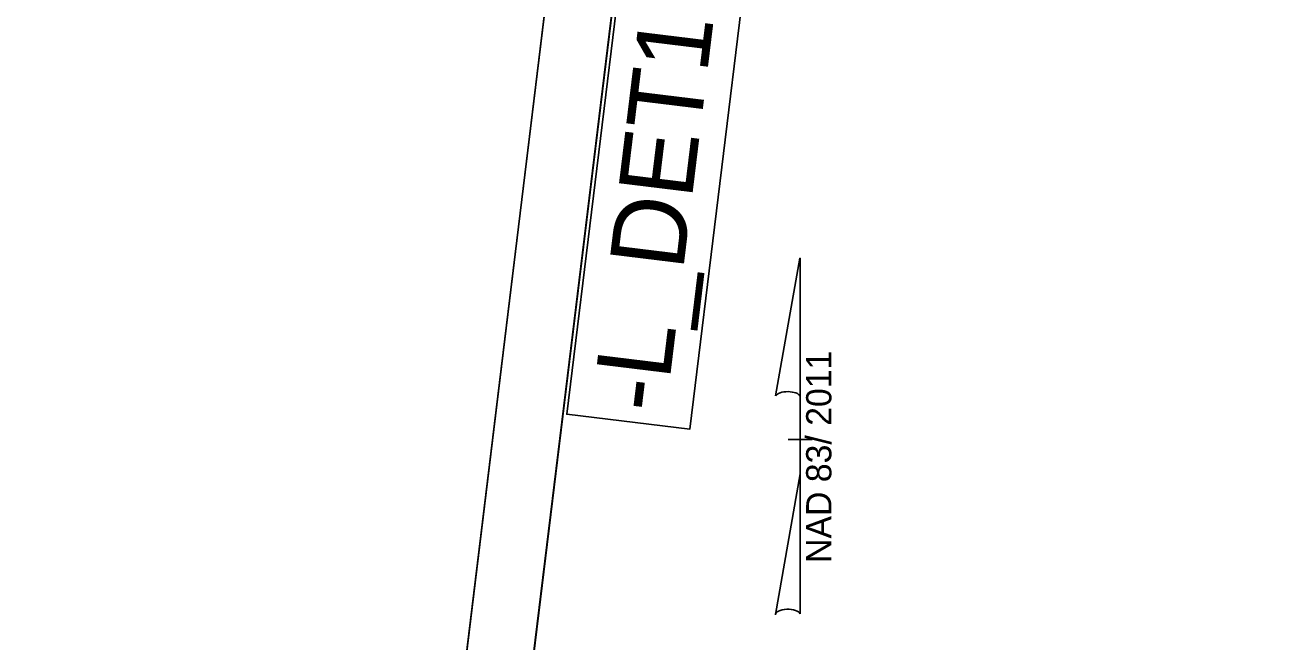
# Model space of a CAD drawing. Extents: x 480344 to 482186, y 488805 to 491553.
# Drawn here: x 480615.8 to 481040.8, y 490157.9 to 490365.2 of the extents above; entities that cross this region are included whole.
import ezdxf

# ---------------------------------------------------------------- set-up
doc = ezdxf.new("R2010")
doc.units = 0
for name, color, linetype in [('Old_Level_1', 7, 'Continuous'), ('Prop Grid Mask', 7, 'Continuous'), ('Prop North Arrow NAD83 for Plan Sheets CELL', 7, 'Continuous'), ('Sheet Cutting Line CELL', 7, 'Continuous'), ('Sheet Layout Plan Border', 7, 'Continuous'), ('Sheet North Arrow Point CELL', 7, 'Continuous'), ('Sheet Plan CELL', 7, 'Continuous'), ('Sheet Plan Layout CELL', 7, 'Continuous'), ('Sheet Plot Border Inside CELL', 7, 'Continuous'), ('Sheet Plot Border Outside CELL', 7, 'Continuous')]:
    doc.layers.add(name, color=color, linetype=linetype)

msp = doc.modelspace()

# ---------------------------------------------------------------- linework, layer by layer
at = {"layer": 'Prop Grid Mask'}
msp.add_lwpolyline([(480817.17, 490390.57), (480798.09, 490234.37), (480839.49, 490229.31), (480858.56, 490385.52)], close=True, dxfattribs=at)
at = {"layer": 'Prop North Arrow NAD83 for Plan Sheets CELL'}
for p, q in [((480868.41, 490240.54), (480876.61, 490286.89)), ((480876.66, 490286.89), (480876.61, 490286.89)), ((480876.66, 490286.89), (480876.61, 490286.89)), ((480876.66, 490286.89), (480876.66, 490239.09)), ((480876.66, 490214.29), (480876.66, 490240.49)), ((480876.66, 490239.09), (480876.66, 490240.44)), ((480872.66, 490225.89), (480872.61, 490225.89)), ((480876.21, 490225.89), (480872.66, 490225.89)), ((480872.71, 490225.89), (480880.71, 490225.89)), ((480876.66, 490214.29), (480868.31, 490167.04)), ((480876.71, 490167.24), (480876.66, 490214.29))]:
    msp.add_line(p, q, dxfattribs=at)
for centre, start_param, end_param in [((480872.54, 490240.04), 0.216388, 2.908219), ((480872.54, 490166.87), 0.201328, 3.141593)]:
    msp.add_ellipse(centre, major_axis=(4.23, -0.03), ratio=0.461098, start_param=start_param, end_param=end_param, dxfattribs=at)
at = {"layer": 'Sheet Cutting Line CELL'}
msp.add_line((480819.86, 490608.9), (480615.75, 488937.82), dxfattribs=at)
at = {"layer": 'Sheet Layout Plan Border'}
msp.add_lwpolyline([(481703.23, 488995.25), (481861.69, 490292.69), (481782.27, 490302.39), (481802.94, 490471.69), (481574.79, 490460.72), (481089.79, 490519.96), (481007.71, 490529.98), (480988.13, 490369.7), (480815.85, 490390.73), (480660.97, 489122.55)], close=True, dxfattribs=at)
at = {"layer": 'Sheet North Arrow Point CELL'}
msp.add_line((480876.66, 490286.89), (480876.66, 490286.89), dxfattribs=at)
msp.add_line((480876.66, 490286.89), (480876.66, 490286.89), dxfattribs=at)
at = {"layer": 'Sheet Plan CELL'}
msp.add_line((480658.28, 489100.33), (480815.85, 490390.73), dxfattribs=at)
msp.add_lwpolyline([(480840.12, 490589.33), (480658.26, 489100.35), (481700.51, 488973.06), (481882.37, 490462)], close=True, dxfattribs=at)
at = {"layer": 'Sheet Plan Layout CELL'}
msp.add_line((480811.11, 490351.81), (480658.28, 489100.33), dxfattribs=at)
at = {"layer": 'Sheet Plot Border Inside CELL'}
msp.add_lwpolyline([(481705.46, 488972.43), (481887.32, 490461.41), (480840.14, 490589.31), (480658.28, 489100.33)], close=True, dxfattribs=at)
at = {"layer": 'Sheet Plot Border Outside CELL'}
msp.add_lwpolyline([(480615.75, 488937.82), (480819.86, 490608.9), (481906.78, 490476.15), (481702.68, 488805.07)], close=True, dxfattribs=at)

# ---------------------------------------------------------------- texts
at = {"layer": 'Old_Level_1'}
msp.add_text('-L_DET1-', height=25, rotation=83.0365, dxfattribs=at).set_placement((480831.37, 490234.39))
at = {"layer": 'Prop North Arrow NAD83 for Plan Sheets CELL'}
msp.add_text('NAD 83/ 2011', height=8.5, rotation=90, dxfattribs=at).set_placement((480887.18, 490184.37))

doc.saveas('drawing.dxf')
